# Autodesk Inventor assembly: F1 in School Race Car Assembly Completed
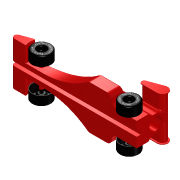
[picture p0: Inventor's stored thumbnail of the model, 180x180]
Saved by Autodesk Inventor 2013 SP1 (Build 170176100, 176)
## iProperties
Created: 2013-01
Part Number: F1 in School Race Car Assembly Completed
Document SubType Name: Assembly
Designer: banachd
Author: banachd
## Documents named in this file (5)
- C:\F1 in Schools\Workspace\Ex3 F1 Race Car Assembly Completed.iam
- C:\F1 in Schools\Workspace\F1 Car Body Completed.ipt
- C:\F1 in Schools\Workspace\Axle.ipt
- C:\F1 in Schools\Workspace\Retaining Ring.ipt
- C:\F1 in Schools\Workspace\Wheel.ipt
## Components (9 placed, 4 different names)
1. F1 Car Body Completed:1 — Mate:1, Mate:2, Insert:1, Insert:2, Insert:3
2. Axle:1 — Insert:4, Insert:6
3. Retaining Ring:1 — Insert:6
4. Axle:2 — Insert:5, Insert:7
5. Retaining Ring:2 — Insert:7
6. Wheel:1 — Insert:1, Insert:5
7. Wheel:2 — Insert:2
8. Wheel:3 — Mate:1, Mate:2, Insert:4
9. Wheel:4 — Insert:3
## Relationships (9: Insert 7, Mate 2)
- Mate:1: F1 Car Body Completed:1 ↔ Wheel:3
- Mate:2: F1 Car Body Completed:1 ↔ Wheel:3
- Insert:1: F1 Car Body Completed:1 ↔ Wheel:1
- Insert:2: F1 Car Body Completed:1 ↔ Wheel:2
- Insert:3: F1 Car Body Completed:1 ↔ Wheel:4
- Insert:4: Axle:1 ↔ Wheel:3
- Insert:5: Axle:2 ↔ Wheel:1
- Insert:6: Axle:1 ↔ Retaining Ring:1
- Insert:7: Axle:2 ↔ Retaining Ring:2
